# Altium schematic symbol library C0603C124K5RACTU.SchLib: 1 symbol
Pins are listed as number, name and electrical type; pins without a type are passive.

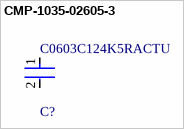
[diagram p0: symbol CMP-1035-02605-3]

## CMP-1035-02605-3
designator C?, comment C0603C124K5RACTU
0603 C 120nF Ceramic Multilayer Capacitor; 50 V; +125degC; X7R Dielec; +/-10%; Manufacturer: KEMET; Capacitance: 0.12 μF; Automotive Grade: Grade 1; Voltage Rating: 50 V; Tolerance: 0.1; Temperature Coefficient: 30ppm/°C; Value: 0.12 μF
footprint FP-C0603C-CF-IPC_B
footprint FP-C0603C-CF-MFG
footprint FP-C0603C-CF-IPC_A
footprint FP-C0603C-CF-IPC_C
pins: 1, 2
